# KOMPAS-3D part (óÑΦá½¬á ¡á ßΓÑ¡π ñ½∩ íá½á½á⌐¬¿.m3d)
File: created 13.03.2016 16:20:00, last saved 13.03.2016 21:14:08.
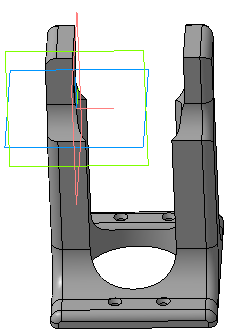
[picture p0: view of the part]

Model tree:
1. Эскиз:1
2. Операция выдавливания:1
     Расстояние 1 = 30
3. Эскиз:2
4. Операция выдавливания:2
     Расстояние 1 = 10
5. Эскиз:3
6. Операция выдавливания:3
     Расстояние 1 = 60
7. Эскиз:4
8. Операция выдавливания:4
     Расстояние 1 = 6
9. Скругление:1
     Радиус = 10
10. Скругление:2
     Радиус = 10
11. Скругление:3
     Радиус = 13
12. Скругление:4
     Радиус = 15
13. Скругление:5
     Радиус = 13
14. Скругление:6
     Радиус = 13
15. Скругление:7
     Радиус = 4
16. Скругление:8
     Радиус = 4
17. Скругление:9
     Радиус = 4
18. Скругление:10
     Радиус = 1
19. Скругление:11
     Радиус = 3
20. Скругление:12
     Радиус = 3
21. Эскиз:5
22. Вырезать элемент выдавливания:1
     Расстояние 1 = 3; Угол 1 = 30
23. Эскиз:6
24. Вырезать элемент выдавливания:2
     Расстояние 1 = 100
